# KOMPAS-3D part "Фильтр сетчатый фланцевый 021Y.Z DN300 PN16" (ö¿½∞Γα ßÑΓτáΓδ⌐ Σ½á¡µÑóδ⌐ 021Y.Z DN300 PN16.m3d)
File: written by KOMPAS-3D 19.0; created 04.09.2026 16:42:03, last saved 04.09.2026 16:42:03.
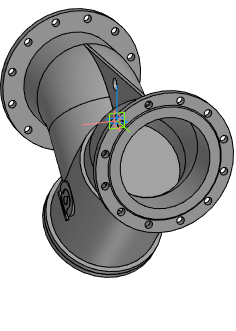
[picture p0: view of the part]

Document properties: Автор: Энергия; Полное имя файла: Z:\3.Личные\sachek\Dendor\_3D для проектировщиков\8.1 Фильтр сетчатый 021Y.Z\021Y.Z_STP\Фильтр сетчатый фланцевый 021Y.Z DN300 PN16.m3d

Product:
- Part/product: Фильтр сетчатый фланцевый 021Y.Z DN300 PN16

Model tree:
1. Операция без истории:1  (labels: Фильтр сетчатый фланцевый 021Y.Z DN300 PN16)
